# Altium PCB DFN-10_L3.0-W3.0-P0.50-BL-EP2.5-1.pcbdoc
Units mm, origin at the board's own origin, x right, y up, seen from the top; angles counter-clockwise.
Board outline 15.85 x 16.97 mm, 2 copper layers (Top Layer, Bottom Layer), stack 0 mm thick; 1 components, 0 nets, 11 pads, 0 vias.
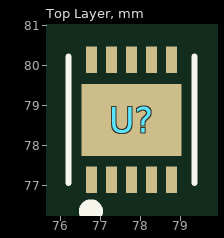
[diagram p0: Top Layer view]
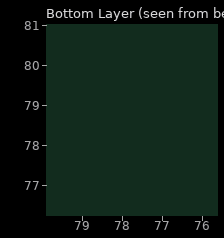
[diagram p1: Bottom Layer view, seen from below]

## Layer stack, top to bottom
Top Layer: signal copper (thickness not stored)
Bottom Layer: signal copper (thickness not stored)

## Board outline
85.702,69.85 69.85,69.85 69.85,86.819 85.702,86.819

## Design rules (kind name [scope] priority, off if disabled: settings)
PasteMaskExpansion "Paste Mask Expansion" [All] p1: expansion=0
SolderMaskExpansion "Solder Mask Expansion" [IsVia] p1: expansion=-25.4 istentingtop=TRUE
SolderMaskExpansion "Solder Mask Expansion" [All] p2: expansion=0.051 istentingtop=FALSE

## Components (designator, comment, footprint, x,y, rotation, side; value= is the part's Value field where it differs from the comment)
U? "" DFN-10_L3.0-W3.0-P0.50-BL-EP2.5-1 77.776,78.636 r0 top

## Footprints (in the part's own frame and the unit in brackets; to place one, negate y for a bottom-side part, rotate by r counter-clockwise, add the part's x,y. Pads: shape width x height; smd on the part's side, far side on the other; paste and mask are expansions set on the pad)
DFN-10_L3.0-W3.0-P0.50-BL-EP2.5-1 [mm]
  rect 0.28x0.665 smd: 1(-1,-1.5) 2(-0.5,-1.5) 3(0,-1.5) 4(0.5,-1.5) 5(1,-1.5) 6(1,1.5) 7(0.5,1.5) 8(0,1.5) 9(-0.5,1.5) 10(-1,1.5)
  rect 2.5x1.8 smd: 11(0,0)
  silkscreen extent -1.58,-2.44 1.58,1.58

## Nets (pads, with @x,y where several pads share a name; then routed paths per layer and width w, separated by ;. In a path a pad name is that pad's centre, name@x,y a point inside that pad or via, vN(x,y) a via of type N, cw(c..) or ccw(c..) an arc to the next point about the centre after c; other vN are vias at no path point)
pads on no net: U?.1 U?.2 U?.3 U?.4 U?.5 U?.6 U?.7 U?.8 U?.9 U?.10 U?.11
